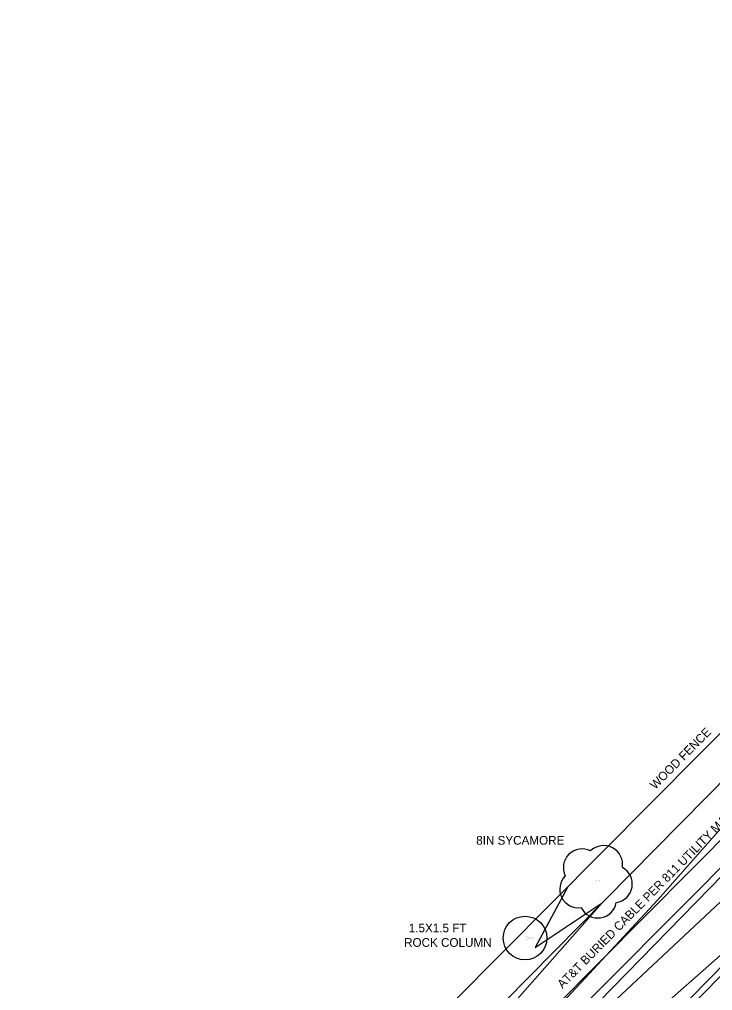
# Model space of a CAD drawing. Extents: x 2250985 to 2256614, y 13788357 to 13792478.
# Drawn here: x 2254026.4 to 2254121.7, y 13790001.6 to 13790135.3 of the extents above; entities that cross this region are included whole.
import ezdxf

# ---------------------------------------------------------------- set-up
doc = ezdxf.new("R2010")
doc.units = 0
for name, color, linetype in [('E_DTM_Grade Break_GB', 7, 'Continuous'), ('E_Road_Pavement_Edge of Pavement_EP', 7, 'Continuous'), ('E_Structure_Column_COL', 7, 'Continuous'), ('E_Structure_Column_COL_ANNO', 7, 'Continuous'), ('E_Structure_Column_COL_Description', 7, 'Continuous'), ('E_Structure_Column_COL_Elevation', 7, 'Continuous'), ('E_Structure_Column_COL_point', 7, 'Continuous'), ('E_Structure_Fence_Wooden Fence_WDFN', 7, 'Continuous'), ('E_Structure_Fence_Wooden Fence_WDFN_ANNO', 7, 'Continuous'), ('E_Utility_Fiber Optic_Fiber Optic Cable_FOC', 7, 'Continuous'), ('E_Utility_Fiber Optic_Fiber Optic Cable_FOC_ANNO', 7, 'Continuous'), ('E_Vegetation_Tree_Tree_TR', 7, 'Continuous'), ('E_Vegetation_Tree_Tree_TR_ANNO', 7, 'Continuous'), ('E_Vegetation_Tree_Tree_TR_Description', 7, 'Continuous'), ('E_Vegetation_Tree_Tree_TR_point', 7, 'Continuous'), ('Minor Contours', 7, 'Continuous')]:
    doc.layers.add(name, color=color, linetype=linetype)

# ---------------------------------------------------------------- blocks, each defined once
blk = doc.blocks.new('TR')
at = {"layer": 'E_Vegetation_Tree_Tree_TR'}
blk.add_line((0, 0), (0, 0), dxfattribs=at)
for centre, radius, start, end in [((-0.18, 0.182), 0.258, 63.1465, 206.2274), ((0.117, 0.224), 0.261, 350.8866, 133.9676), ((0.253, -0.044), 0.258, 278.5736, 61.6546), ((-0.229, -0.114), 0.258, 135.0205, 278.1015), ((0.037, -0.254), 0.258, 206.7946, 349.8756)]:
    blk.add_arc(centre, radius, start, end, dxfattribs=at)
blk = doc.blocks.new('COL')
at = {"layer": 'E_Structure_Column_COL'}
blk.add_circle((0, 0), 0.3, dxfattribs=at)

msp = doc.modelspace()

# ---------------------------------------------------------------- linework, layer by layer
at = {"layer": 'E_DTM_Grade Break_GB'}
for points in [[(2254047.14, 13789943.13), (2254070.48, 13789965.82), (2254144.51, 13790040.31), (2254214.64, 13790111.62), (2254222.13, 13790118.03), (2254261.74, 13790158.16), (2254331.19, 13790229.94)], [(2254034.37, 13789937.97), (2254037.01, 13789947.54), (2254040.16, 13789950.61), (2254065.19, 13789971.77), (2254138.29, 13790045.87), (2254209.98, 13790117.05)], [(2254039.08, 13789930.55), (2254045.62, 13789931.95), (2254054.44, 13789936.9), (2254057.73, 13789938.88), (2254077.58, 13789958.69), (2254151.88, 13790034.37), (2254221.32, 13790105.43)]]:
    msp.add_lwpolyline(points, dxfattribs=at)
at = {"layer": 'E_Road_Pavement_Edge of Pavement_EP'}
msp.add_lwpolyline([(2254054.06, 13789934.31), (2254054.36, 13789934.37), (2254078.2, 13789958.12), (2254152.66, 13790033.98), (2254221.89, 13790104.87), (2254268.04, 13790151.73), (2254338.14, 13790223.62)], dxfattribs=at)
at = {"layer": 'E_Structure_Fence_Wooden Fence_WDFN'}
msp.add_lwpolyline([(2254058.69, 13789972.46), (2254133.73, 13790048.05), (2254207.27, 13790121.49), (2254212.46, 13790126.35)], dxfattribs=at)
at = {"layer": 'E_Utility_Fiber Optic_Fiber Optic Cable_FOC'}
for points in [[(2255032.95, 13790952.64), (2255003.31, 13790917.86), (2254946.65, 13790859.31), (2254901.94, 13790813.52), (2254833.06, 13790741.96), (2254719.46, 13790626.58), (2254679.73, 13790589.47), (2254575.8, 13790484.36), (2254537.8, 13790440.4), (2254506.03, 13790406.14), (2254463.43, 13790363.14), (2254414.76, 13790317.41), (2254378.78, 13790279.87), (2254273.85, 13790176.15), (2254188.13, 13790088.11), (2254093.61, 13789992.87), (2254044.6, 13789948.83), (2254024.52, 13789950.57), (2253953.86, 13790019.75)], [(2255036.19, 13790949.67), (2255006.11, 13790915.3), (2254948.5, 13790856.97), (2254903.08, 13790810.98), (2254834.19, 13790740.94), (2254720.9, 13790624.94), (2254681.69, 13790585.77), (2254577.09, 13790483.1), (2254539.49, 13790439.08), (2254507.35, 13790404.45), (2254464.72, 13790361.81), (2254418.33, 13790314.06), (2254380.92, 13790278.17), (2254276.09, 13790173.83), (2254189.76, 13790085.78), (2254096.65, 13789990.4), (2254035.89, 13789928.99), (2253999.95, 13789892.08), (2253925.3, 13789814.47), (2253839.93, 13789726.81), (2253809.07, 13789696.5), (2253784.83, 13789670.85)]]:
    msp.add_lwpolyline(points, dxfattribs=at)
at = {"layer": 'Minor Contours'}
for points in [[(2254071.02, 13789965.28), (2254122.86, 13790013.9), (2254148.83, 13790036.83), (2254170.34, 13790057.09), (2254190.46, 13790073.85), (2254191.97, 13790074.89), (2254193.22, 13790075.52), (2254206.69, 13790078.22), (2254211.57, 13790078.54), (2254211.56, 13790078.27), (2254212.45, 13790078.31), (2254212.41, 13790067.75), (2254211.94, 13790061.93), (2254206.71, 13790055.74), (2254199.84, 13790047.93), (2254175.56, 13790019.12)], [(2254148.44, 13790062.74), (2254158.76, 13790068.31), (2254162.34, 13790069.74), (2254156.86, 13790061.86), (2254140.49, 13790043.91), (2254114.19, 13790014.11), (2254069.97, 13789966.39)], [(2254100.98, 13789987.23), (2254135.61, 13790017.8), (2254135.75, 13790017.67), (2254138.56, 13790019.61), (2254140.87, 13790019.14), (2254154.54, 13790020.32), (2254154.62, 13790020.33), (2254154.58, 13790019.39), (2254152.61, 13790015.19), (2254149.46, 13789997.91)], [(2254101.84, 13790015.92), (2254097.32, 13790007.53), (2254106.57, 13790013.71), (2254083.57, 13789987.65)]]:
    msp.add_lwpolyline(points, dxfattribs=at)

# ---------------------------------------------------------------- block references
at = {"layer": 'E_Structure_Column_COL', "xscale": 10, "yscale": 10}
msp.add_blockref('COL', (2254095.94, 13790008.85), dxfattribs=at)
at = {"layer": 'E_Vegetation_Tree_Tree_TR', "xscale": 10, "yscale": 10}
msp.add_blockref('TR', (2254105.59, 13790016.73), dxfattribs=at)

# ---------------------------------------------------------------- texts
at = {"layer": 'E_Structure_Column_COL_ANNO'}
for s, p in [('1.5X1.5 FT ', (2254079.95, 13790009.64)), ('ROCK COLUMN', (2254079.3, 13790007.64))]:
    msp.add_text(s, height=1.2, dxfattribs=at).set_placement(p)
at = {"layer": 'E_Structure_Column_COL_Description'}
msp.add_text('1.5X1.5 SQUARE COLUMN', height=0.06, dxfattribs=at).set_placement((2254096.09, 13790008.82))
at = {"layer": 'E_Structure_Column_COL_Elevation'}
msp.add_text('651.97', height=0.06, dxfattribs=at).set_placement((2254096.09, 13790008.64))
at = {"layer": 'E_Structure_Column_COL_point'}
msp.add_text('6498', height=0.06, dxfattribs=at).set_placement((2254096.09, 13790009))
at = {"layer": 'E_Structure_Fence_Wooden Fence_WDFN_ANNO'}
msp.add_text('WOOD FENCE', height=1.2, rotation=45.2092, dxfattribs=at).set_placement((2254113.85, 13790029.23))
at = {"layer": 'E_Utility_Fiber Optic_Fiber Optic Cable_FOC_ANNO'}
msp.add_text('AT&T BURIED CABLE PER 811 UTILITY MARKINGS', height=1.2, rotation=45.4185, dxfattribs=at).set_placement((2254101.1, 13790001.83))
at = {"layer": 'E_Vegetation_Tree_Tree_TR_ANNO'}
msp.add_text('8IN SYCAMORE', height=1.2, dxfattribs=at).set_placement((2254089.22, 13790021.7))
at = {"layer": 'E_Vegetation_Tree_Tree_TR_Description'}
msp.add_text('8IN SYCAMORE', height=0.06, dxfattribs=at).set_placement((2254105.65, 13790016.7))
at = {"layer": 'E_Vegetation_Tree_Tree_TR_point'}
msp.add_text('6413', height=0.06, dxfattribs=at).set_placement((2254105.48, 13790016.79))

doc.saveas('drawing.dxf')
